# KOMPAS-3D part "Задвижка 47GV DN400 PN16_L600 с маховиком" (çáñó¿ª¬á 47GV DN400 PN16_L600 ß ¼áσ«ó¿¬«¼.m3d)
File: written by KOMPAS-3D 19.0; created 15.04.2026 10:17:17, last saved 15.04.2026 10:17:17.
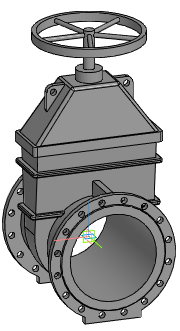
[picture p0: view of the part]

Document properties: Автор: Евгений; Полное имя файла: Z:\3.Личные\kachalov\3d для проектировщиков\2.1 Тип 47GV, 47GV.Z\Задвижка 47GV_DN40-DN600\stp_Задвижка 47GV\Задвижка 47GV DN400 PN16_L600 с маховиком.m3d

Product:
- Part/product: Задвижка 47GV DN400 PN16_L600 с маховиком

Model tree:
1. Операция без истории:1  (labels: Задвижка 47GV DN400 PN16_L600 с маховиком)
